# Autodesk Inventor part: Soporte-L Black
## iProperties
Created: 2008-01
Part Number: Soporte-L Black
Document SubType Name: Modeling
Designer: eruiz-tagle
Mass: 1.15908 g
Surface Area: 19.3833 cm^2
Volume: 1.15908 cm^3
Density: 1 g/cm^3
Author: eruiz-tagle
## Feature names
1. Extrusion1
2. Fillet1
3. Fillet2
4. Fillet3
5. Hole1
6. Fillet4
7. Rectangular Pattern1
8. Circular Pattern1
9. Mirror1
